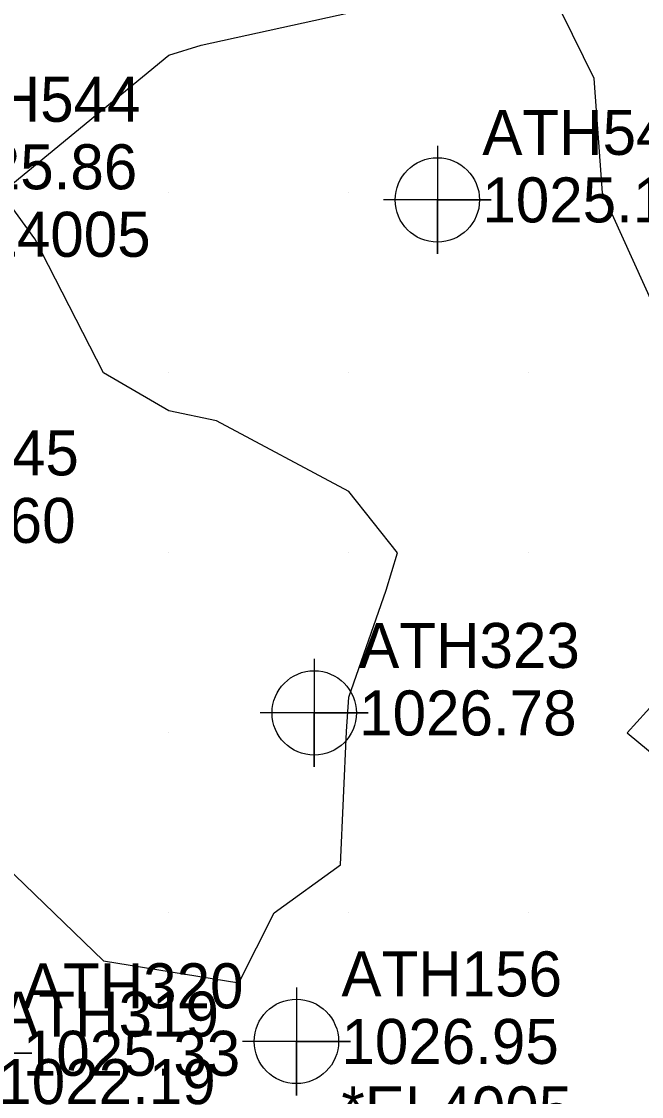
# Model space of a CAD drawing. Extents: x 1213164 to 1213550, y 766120 to 766870.
# Drawn here: x 1213371.8 to 1213406.3, y 766479.8 to 766539.5 of the extents above; entities that cross this region are included whole.
import ezdxf

# ---------------------------------------------------------------- set-up
doc = ezdxf.new("R2010")
doc.units = 0
for name, color, linetype in [('Default', 7, 'Continuous'), ('Exist DTM Breakline Cogo Comment', 7, 'Continuous'), ('Exist DTM Breakline Cogo Elevation', 7, 'Continuous'), ('Exist DTM Breakline Cogo Number', 7, 'Continuous'), ('Exist DTM Breakline Cogo Point CELL', 7, 'Continuous'), ('Exist DTM Drainline Cogo Elevation', 7, 'Continuous'), ('Exist DTM Drainline Cogo Number', 7, 'Continuous'), ('Exist DTM QL2 LIDAR Elevation Point', 7, 'Continuous'), ('Exist DTM Regular Point CELL', 7, 'Continuous'), ('Exist DTM Regular Point Cogo Elevation', 7, 'Continuous'), ('Exist DTM Regular Point Cogo Number', 7, 'Continuous')]:
    doc.layers.add(name, color=color, linetype=linetype)

msp = doc.modelspace()

# ---------------------------------------------------------------- linework, layer by layer
at = {"layer": 'Default'}
for points in [[(1213369.783, 766493.692), (1213376.375, 766487.335), (1213383.89, 766486.11), (1213385.859, 766490), (1213389.538, 766492.677), (1213389.872, 766500.073), (1213390, 766501.99), (1213392.081, 766507.919), (1213392.709, 766510), (1213390, 766513.406), (1213382.66, 766517.34), (1213380, 766517.885), (1213376.377, 766520), (1213372.553, 766527.447), (1213370.697, 766530), (1213380, 766537.646), (1213381.804, 766538.196), (1213390, 766539.988)], [(1213407.516, 766522.484), (1213404.112, 766530), (1213403.652, 766536.348), (1213401.853, 766540)], [(1213410, 766509.404), (1213407.624, 766502.376), (1213405.484, 766500), (1213410, 766496.265), (1213412.764, 766497.236), (1213415.014, 766500), (1213410, 766509.404)]]:
    msp.add_lwpolyline(points, dxfattribs=at)
at = {"layer": 'Exist DTM Breakline Cogo Point CELL'}
for points in [[(1213387.094, 766485.859), (1213387.094, 766479.859), (1213387.094, 766482.859), (1213390.094, 766482.859), (1213384.094, 766482.859)], [(1213369.388, 766485.2), (1213369.388, 766479.2), (1213369.388, 766482.2), (1213372.388, 766482.2), (1213366.388, 766482.2)]]:
    msp.add_lwpolyline(points, dxfattribs=at)
msp.add_circle((1213387.094, 766482.859), 2.344, dxfattribs=at)
at = {"layer": 'Exist DTM QL2 LIDAR Elevation Point'}
for p, q in [((1213380, 766530), (1213380, 766530)), ((1213390, 766530), (1213390, 766530)), ((1213400, 766530), (1213400, 766530)), ((1213380, 766520), (1213380, 766520)), ((1213390, 766520), (1213390, 766520)), ((1213400, 766520), (1213400, 766520)), ((1213380, 766510), (1213380, 766510)), ((1213390, 766510), (1213390, 766510)), ((1213400, 766510), (1213400, 766510)), ((1213380, 766500), (1213380, 766500)), ((1213390, 766500), (1213390, 766500)), ((1213400, 766500), (1213400, 766500)), ((1213380, 766490), (1213380, 766490)), ((1213390, 766490), (1213390, 766490)), ((1213400, 766490), (1213400, 766490)), ((1213390, 766480), (1213390, 766480)), ((1213400, 766480), (1213400, 766480))]:
    msp.add_line(p, q, dxfattribs=at)
at = {"layer": 'Exist DTM Regular Point CELL'}
for points in [[(1213394.928, 766532.603), (1213394.928, 766526.603), (1213394.928, 766529.603), (1213397.928, 766529.603), (1213391.928, 766529.603)], [(1213388.083, 766504.104), (1213388.083, 766498.104), (1213388.083, 766501.104), (1213391.083, 766501.104), (1213385.083, 766501.104)]]:
    msp.add_lwpolyline(points, dxfattribs=at)
for centre in [(1213394.928, 766529.603), (1213388.083, 766501.104)]:
    msp.add_circle(centre, 2.344, dxfattribs=at)

# ---------------------------------------------------------------- texts
at = {"layer": 'Exist DTM Breakline Cogo Comment'}
for p in [(1213366.165, 766526.442), (1213389.594, 766477.859)]:
    msp.add_text('*EL4005', height=2.5, dxfattribs=at).set_placement(p)
at = {"layer": 'Exist DTM Breakline Cogo Elevation'}
for s, p in [('1025.86', (1213366.165, 766530.192)), ('1026.95', (1213389.594, 766481.609)), ('1025.33', (1213371.888, 766480.95))]:
    msp.add_text(s, height=2.5, dxfattribs=at).set_placement(p)
at = {"layer": 'Exist DTM Breakline Cogo Number'}
for s, p in [('ATH544', (1213366.165, 766533.942)), ('ATH156', (1213389.594, 766485.359)), ('ATH320', (1213371.888, 766484.7))]:
    msp.add_text(s, height=2.5, dxfattribs=at).set_placement(p)
at = {"layer": 'Exist DTM Drainline Cogo Elevation'}
msp.add_text('1022.19', height=2.5, dxfattribs=at).set_placement((1213370.524, 766479.377))
at = {"layer": 'Exist DTM Drainline Cogo Number'}
msp.add_text('ATH319', height=2.5, dxfattribs=at).set_placement((1213370.524, 766483.127))
at = {"layer": 'Exist DTM Regular Point Cogo Elevation'}
for s, p in [('1025.13', (1213397.428, 766528.353)), ('1026.60', (1213362.736, 766510.55)), ('1026.78', (1213390.583, 766499.854))]:
    msp.add_text(s, height=2.5, dxfattribs=at).set_placement(p)
at = {"layer": 'Exist DTM Regular Point Cogo Number'}
for s, p in [('ATH546', (1213397.428, 766532.103)), ('ATH545', (1213362.736, 766514.3)), ('ATH323', (1213390.583, 766503.604))]:
    msp.add_text(s, height=2.5, dxfattribs=at).set_placement(p)

doc.saveas('drawing.dxf')
